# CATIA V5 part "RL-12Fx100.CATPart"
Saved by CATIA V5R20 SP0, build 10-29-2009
Part number: _RL-12Fx100
Definition: NONE
Nomenclature: _RL-12Fx100
Source: Unknown
Description: PART-_RL-12Fx100-DESC
Bounding box of the stored display mesh (mm): x -100 to 12.5, y -6.8 to 6.8, z -6.8 to 6.8
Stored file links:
  C:\Users\Utente\Desktop\IO LAVORO\3D X SITO CF\X SITO\PLASTICA\RLF\RL-12Fx100.CATPart
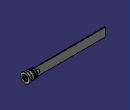
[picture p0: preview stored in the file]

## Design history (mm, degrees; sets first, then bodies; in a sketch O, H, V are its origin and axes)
Body1 "_RL-12Fx100" (main body)
  Solid1: solid without history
